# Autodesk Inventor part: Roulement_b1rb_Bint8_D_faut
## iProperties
Created: 2011-10
Part Number: Roulement_b1rb_Bint8_D_faut
Document SubType Name: Modeling
Designer: Bruno
Author: Bruno
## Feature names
1. Base1
